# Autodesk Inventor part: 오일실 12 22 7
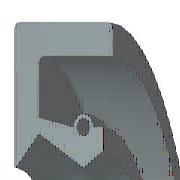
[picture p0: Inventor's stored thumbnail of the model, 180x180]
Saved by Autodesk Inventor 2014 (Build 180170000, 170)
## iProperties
Created: 2012-02
Part Number: 오일실 12 22 7
Material: 고무
Description: 오일-실
Document SubType Name: Modeling
Standard: KS B 2804
Designer: mduedu
Standards Organization: KS
Language: ko-KR
Size Designation: D - 12 22 7
Categories: <MemberInstance><Categories><Category DisplayName="샤프트 부품" InternalName="7f7aeb1f-a693-4053-b835-cee3144e0d98" Mnemonic="SHFT"><Category DisplayName="실링" Intern
Density: 0.93 g/cm^3
Mass: 1.25383 g
Surface Area: 18.4996 cm^2
Volume: 1.3482 cm^3
Appearance: 고무 - 검은색 - 버전 1.1
IsCustomPart: 1
Author: mduedu
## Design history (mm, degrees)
revolve "본체" stored, may be unused: angle "d17" = 90 deg
revolve "스프링1" stored, may be unused: angle "d18" = 90 deg
body "Solid1"
sketch "스케치1"
  geometry: L1 (0, 11)-(7, 11); L2 (7, 9.25)-(1.75, 9.25); L3 (1.75, 7.75)-(4.9, 6); L4 (4.9, 6)-(0, 6); L5 (0, 0)-(9.586, 0) reference; L6 (4.9, 6)-(6.3, 6.875); L7 (0, 18)-(0, -3) reference; L8 (-1.941, 0)-(11.507, 0) reference; L9 (4.2, 8.1)-(1.75, 8.59); L10 (1.75, 8.59)-(1.75, 9.25); L11 (0, 11)-(0, 6.088); L12 (4.9, 6)-(0, 6); L13 (1.75, 7.75)-(0.152, 6.028); L14 (7, 11)-(7, 9.25); L15 (5.6, 8.1)-(6.3, 8.1); L16 (6.3, 8.1)-(6.3, 6.875); C1 r 0.455 at (4.9, 8.1); A1 r 0.7 centre (4.9, 8.1) between (5.6, 8.1) and (4.2, 8.1); A2 r 0.088 centre (0.088, 6.088) between (0, 6.088) and (0.152, 6.028); 1 further point
  constraints: 28 end point, 5 horizontal alignment, 5 point on line, 4 point on circle, 4 vertical alignment, 3 centre point, 3 tangent, 2 collinear, 2 horizontal, 2 perpendicular, 1 coincident, 1 parallel
  dimensions: "d0" = 22 diameter of L1 L5 (= SD2); "d1" = 1.75 distance of L1.end L2.start (= SD); "d2" = 0.91 diameter of C1 (= SPDI); "d3" = 1.4 diameter of A1 (= SPDA); "d4" = 12 diameter of L3.end L5 (= NND); "d5" = 15.5 diameter of L3.start L5 (= TKDM); "d7" = 17.18 diameter of L9.end L5 (= TKDM + 0.24 x SWDT); "d8" = 1.75 distance between parallel lines of L11 L10 (= SD); "d9" = 4.9 distance from line of L11 C1.centre (= SPDST); "d10" = 16.2 diameter of C1.centre L5 (= HLDM); "d11" = 0.0875 radius of A2 (= 0.25 x LAB); "d12" = 6.3 distance between parallel lines of L11 L16 (= SDI); "d13" = 13.75 diameter of L6.end L5 (= ABDM); "d14" = 7 distance from line of L11 L1.end (= SWDT)
fillet "모깎기1" dims "d6" = 0.3 (= RR)
other parameters: "SD2" = 22 [user parameter; used in 1 equation term], "SWDT" = 7 [user parameter; used in 2 equation terms], "RR" = 0.3 [user parameter; used in 1 equation term], "SD" = 1.75 [user parameter; used in 2 equation terms], "NND" = 12 [user parameter; used in 1 equation term], "SPDA" = 1.4 [user parameter; used in 1 equation term], "SPDI" = 0.91 [user parameter; used in 1 equation term], "TKDM" = 15.5 [user parameter; used in 2 equation terms], "HLDM" = 16.2 [user parameter; used in 1 equation term], "ABDM" = 13.75 [user parameter; used in 1 equation term], "SDI" = 6.3 [user parameter; used in 1 equation term], "SPDST" = 4.9 [user parameter; used in 1 equation term], "LAB" = 0.35 [user parameter; used in 1 equation term], "d15" = 0, "d16" = 0, "d19" = 0
